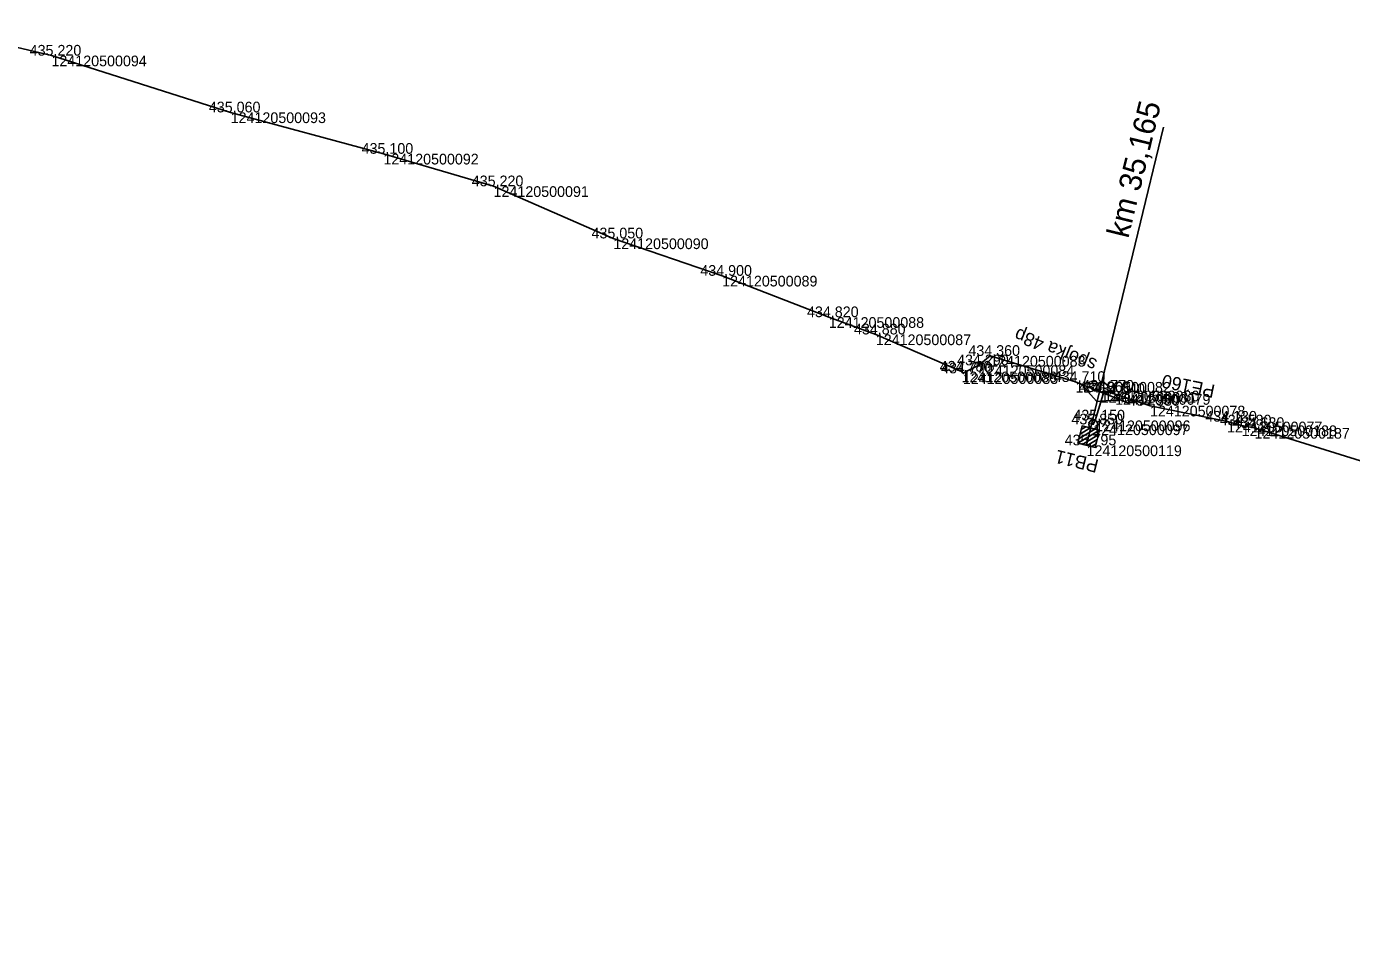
# Model space of a CAD drawing. Extents: x -637342 to -635997, y -1153616 to -1153154.
# Drawn here: x -636344.1 to -636195.2, y -1153579.5 to -1153477.2 of the extents above; entities that cross this region are included whole.
import ezdxf

# ---------------------------------------------------------------- set-up
doc = ezdxf.new("R2010")
doc.units = 0
for name, color, linetype in [('Vrstva 27', 7, 'Continuous'), ('Vrstva 28', 7, 'Continuous'), ('Vrstva 3', 7, 'Continuous'), ('Vrstva 35', 7, 'Continuous'), ('Vrstva 60', 7, 'Continuous'), ('Vrstva 61', 7, 'Continuous')]:
    doc.layers.add(name, color=color, linetype=linetype)

msp = doc.modelspace()

# ---------------------------------------------------------------- linework, layer by layer
at = {"layer": 'Vrstva 27'}
msp.add_line((-636224.18, -1153521.89), (-636224.2, -1153521.99), dxfattribs=at)
msp.add_circle((-636224.19, -1153521.94), 0.5, dxfattribs=at)
at = {"layer": 'Vrstva 28'}
for p, q in [((-636220.11, -1153519.59), (-636226.59, -1153517.01)), ((-636225.51, -1153517.44), (-636222.92, -1153517.22)), ((-636223.78, -1153519.38), (-636225.51, -1153517.44)), ((-636222.92, -1153517.22), (-636221.19, -1153519.16)), ((-636221.19, -1153519.16), (-636223.78, -1153519.38))]:
    msp.add_line(p, q, dxfattribs=at)
for points in [[(-636209.15, -1153521.63), (-636217.81, -1153519.84), (-636221.73, -1153518.53), (-636222.97, -1153518.15), (-636223.35, -1153518.3), (-636226.18, -1153517.17), (-636235.77, -1153514.24), (-636237.04, -1153515.3), (-636238.84, -1153516.2), (-636238.99, -1153516.01), (-636248.63, -1153511.83), (-636253.91, -1153509.89), (-636265.9, -1153505.24), (-636278.13, -1153501.04), (-636291.59, -1153495.18), (-636303.97, -1153491.53), (-636321.14, -1153486.88), (-636341.28, -1153480.5), (-636355.12, -1153477.23)], [(-636222.97, -1153518.15), (-636223.97, -1153521.5), (-636224.19, -1153521.94)], [(-636021.02, -1153579.48), (-636020.91, -1153578.04), (-636020.46, -1153577.28), (-636021.11, -1153576.37), (-636037.55, -1153569.01), (-636052.88, -1153562.53), (-636059.75, -1153559.88), (-636065.86, -1153557.92), (-636081.04, -1153554.39), (-636105.63, -1153547.85), (-636120.42, -1153543.97), (-636134.85, -1153539.86), (-636139.76, -1153538.48), (-636158.58, -1153534.6), (-636167.44, -1153532.46), (-636171.24, -1153531.81), (-636183.59, -1153529.07), (-636192.48, -1153526.55), (-636206.06, -1153522.34), (-636207.51, -1153522.06), (-636209.15, -1153521.63)]]:
    msp.add_lwpolyline(points, dxfattribs=at)
at = {"layer": 'Vrstva 3'}
for p, q in [((-636224.94, -1153524.29), (-636216.29, -1153488.54)), ((-636223.49, -1153522.59), (-636225.91, -1153524.06)), ((-636224.01, -1153522.46), (-636225.79, -1153523.54)), ((-636224.52, -1153522.34), (-636225.66, -1153523.03)), ((-636225.04, -1153522.21), (-636225.53, -1153522.51)), ((-636223.62, -1153523.1), (-636225.4, -1153524.18)), ((-636223.75, -1153523.62), (-636224.88, -1153524.31)), ((-636223.87, -1153524.14), (-636224.37, -1153524.44))]:
    msp.add_line(p, q, dxfattribs=at)
msp.add_lwpolyline([(-636223.97, -1153524.53), (-636225.91, -1153524.06), (-636225.44, -1153522.11), (-636223.49, -1153522.59)], close=True, dxfattribs=at)
at = {"layer": 'Vrstva 35'}
msp.add_line((-636209.15, -1153521.63), (-636217.81, -1153519.84), dxfattribs=at)
at = {"layer": 'Vrstva 60'}
for p, q in [((-636341.28, -1153480.5), (-636341.28, -1153480.5)), ((-636321.14, -1153486.88), (-636321.14, -1153486.88)), ((-636303.97, -1153491.53), (-636303.97, -1153491.53)), ((-636291.59, -1153495.18), (-636291.59, -1153495.18)), ((-636278.13, -1153501.04), (-636278.13, -1153501.04)), ((-636265.9, -1153505.24), (-636265.9, -1153505.24)), ((-636253.91, -1153509.89), (-636253.91, -1153509.89)), ((-636248.63, -1153511.83), (-636248.63, -1153511.83)), ((-636237.04, -1153515.3), (-636237.04, -1153515.3)), ((-636235.77, -1153514.24), (-636235.77, -1153514.24)), ((-636238.99, -1153516.01), (-636238.99, -1153516.01)), ((-636238.84, -1153516.2), (-636238.84, -1153516.2)), ((-636226.18, -1153517.17), (-636226.18, -1153517.17)), ((-636223.35, -1153518.3), (-636223.35, -1153518.3)), ((-636222.97, -1153518.15), (-636222.97, -1153518.15)), ((-636221.73, -1153518.53), (-636221.73, -1153518.53)), ((-636217.81, -1153519.84), (-636217.81, -1153519.84)), ((-636224.19, -1153521.94), (-636224.19, -1153521.94)), ((-636223.97, -1153521.5), (-636223.97, -1153521.5)), ((-636209.15, -1153521.63), (-636209.15, -1153521.63)), ((-636207.51, -1153522.06), (-636207.51, -1153522.06)), ((-636206.06, -1153522.34), (-636206.06, -1153522.34)), ((-636224.94, -1153524.29), (-636224.94, -1153524.29))]:
    msp.add_line(p, q, dxfattribs=at)

# ---------------------------------------------------------------- texts
at = {"layer": 'Vrstva 28'}
msp.add_text('spojka 48p', height=1.5, rotation=158.2335, dxfattribs=at).set_placement((-636223.66, -1153514.69))
at = {"layer": 'Vrstva 3'}
for s, height, rotation, p in [('km 35,165', 2.5, 76.2586, (-636220.26, -1153501.12)), ('PB11', 1.5, 166.2586, (-636223.48, -1153525.94))]:
    msp.add_text(s, height=height, rotation=rotation, dxfattribs=at).set_placement(p)
at = {"layer": 'Vrstva 35'}
msp.add_text('PE160', height=1.5, rotation=168.3216, dxfattribs=at).set_placement((-636210.41, -1153517.52))
at = {"layer": 'Vrstva 60'}
for s, p in [('124120500094', (-636341.28, -1153481.7)), ('124120500093', (-636321.14, -1153488.08)), ('124120500092', (-636303.97, -1153492.73)), ('124120500091', (-636291.59, -1153496.38)), ('124120500090', (-636278.13, -1153502.24)), ('124120500089', (-636265.9, -1153506.44)), ('124120500088', (-636253.91, -1153511.09)), ('124120500087', (-636248.63, -1153513.03)), ('124120500084', (-636237.04, -1153516.5)), ('124120500083', (-636235.77, -1153515.44)), ('124120500086', (-636238.99, -1153517.21)), ('124120500085', (-636238.84, -1153517.4)), ('124120500082', (-636226.18, -1153518.37)), ('124120500081', (-636223.35, -1153519.5)), ('124120500080', (-636222.97, -1153519.35)), ('124120500079', (-636221.73, -1153519.73)), ('124120500078', (-636217.81, -1153521.04)), ('124120500097', (-636224.19, -1153523.14)), ('124120500096', (-636223.97, -1153522.7)), ('124120500077', (-636209.15, -1153522.83)), ('124120500188', (-636207.51, -1153523.26)), ('124120500187', (-636206.06, -1153523.54)), ('124120500119', (-636224.94, -1153525.5))]:
    msp.add_text(s, height=1.2, dxfattribs=at).set_placement(p)
at = {"layer": 'Vrstva 61'}
for s, p in [('435.220', (-636343.73, -1153480.5)), ('435.060', (-636323.59, -1153486.88)), ('435.100', (-636306.42, -1153491.53)), ('435.220', (-636294.04, -1153495.18)), ('435.050', (-636280.58, -1153501.04)), ('434.900', (-636268.35, -1153505.24)), ('434.820', (-636256.36, -1153509.89)), ('434.880', (-636251.08, -1153511.83)), ('434.360', (-636238.22, -1153514.24)), ('434.780', (-636241.44, -1153516.01)), ('434.770', (-636241.29, -1153516.2)), ('434.290', (-636239.49, -1153515.3)), ('434.710', (-636228.63, -1153517.17)), ('434.770', (-636225.42, -1153518.15)), ('434.860', (-636225.8, -1153518.3)), ('434.640', (-636224.18, -1153518.53)), ('434.380', (-636220.26, -1153519.84)), ('435.850', (-636226.64, -1153521.94)), ('435.150', (-636226.42, -1153521.5)), ('434.130', (-636211.6, -1153521.63)), ('434.580', (-636209.96, -1153522.06)), ('434.630', (-636208.51, -1153522.34)), ('435.795', (-636227.4, -1153524.29))]:
    msp.add_text(s, height=1.2, dxfattribs=at).set_placement(p)

doc.saveas('drawing.dxf')
